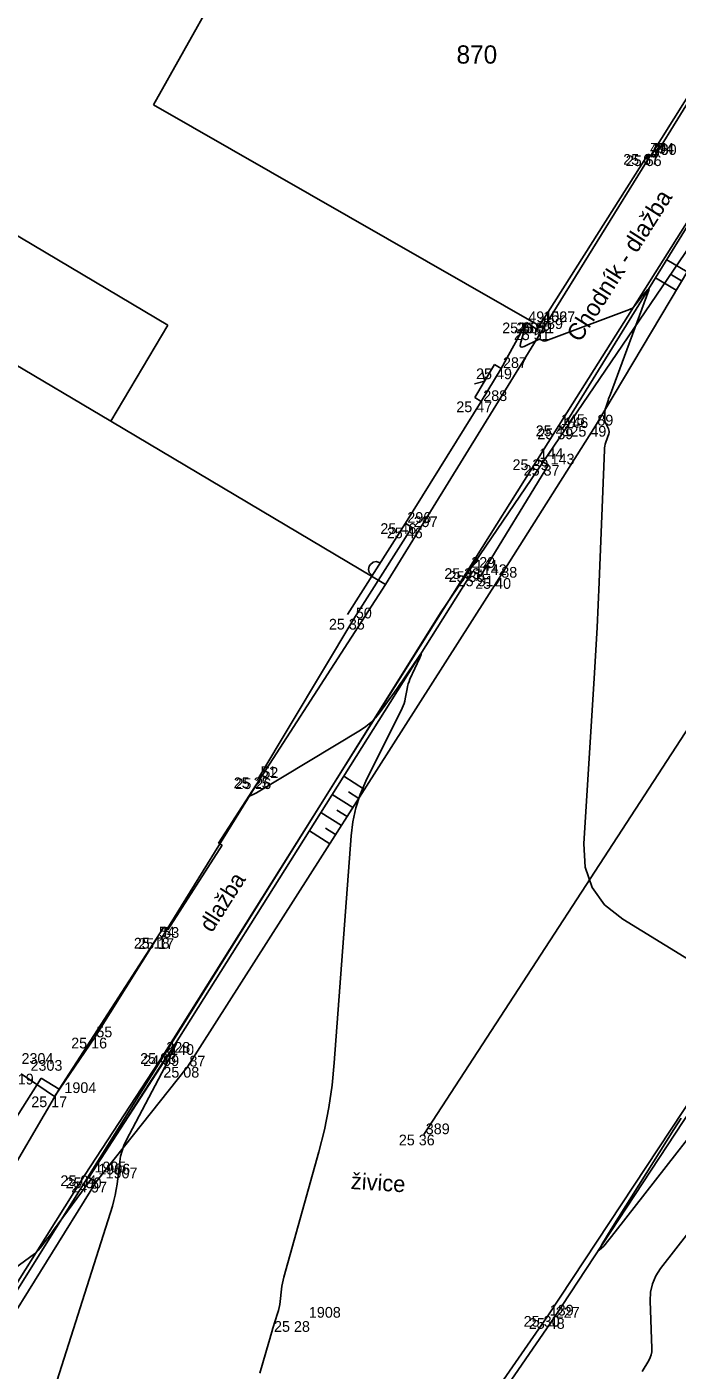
# Model space of a CAD drawing. Extents: x -702257 to -701487, y -1009871 to -1008841.
# Drawn here: x -701793.04 to -701777.89, y -1009417.21 to -1009385.88 of the extents above; entities that cross this region are included whole.
import ezdxf

# ---------------------------------------------------------------- set-up
doc = ezdxf.new("R2010")
doc.units = 0
for name, color, linetype in [('Ex_Major Contours', 7, 'Continuous'), ('Ex_Minor Contours', 7, 'Continuous'), ('Z_body', 7, 'Continuous'), ('Z_body_cisla', 7, 'Continuous'), ('Z_body_vysky_redukovane', 7, 'Continuous'), ('Z_budova', 7, 'Continuous'), ('Z_hrany_paty', 7, 'Continuous'), ('Z_katastr_cisla_stavebni', 7, 'Continuous'), ('Z_katastr_hranice', 7, 'Continuous'), ('Z_katastr_vnitrni_kresba', 7, 'Continuous'), ('Z_komunikace', 7, 'Continuous'), ('Z_obruba', 7, 'Continuous'), ('Z_ploty', 7, 'Continuous'), ('Z_ploty_znacky', 7, 'Continuous'), ('Z_popisy', 7, 'Continuous'), ('Z_technicke_srafy', 7, 'Continuous'), ('Z_VDZ12_prerusovana', 7, 'Continuous'), ('Z_vstupy', 7, 'Continuous')]:
    doc.layers.add(name, color=color, linetype=linetype)

# ---------------------------------------------------------------- blocks, each defined once
blk = doc.blocks.new('POINT_DISPLAY')
blk.add_line((0, 0), (0, 0))
blk = doc.blocks.new('Z216_1')
for p, q in [((-0.175, 0), (-0.15, 0.1)), ((-0.15, 0.1), (-0.1, 0.15)), ((-0.1, 0.15), (-0.025, 0.175)), ((-0.025, 0.175), (0.025, 0.175)), ((0.025, 0.175), (0.1, 0.15)), ((0.1, 0.15), (0.15, 0.1)), ((0.15, 0.1), (0.175, 0))]:
    blk.add_line(p, q)
blk = doc.blocks.new('Z212_1')
for p, q in [((-0.175, 0.175), (0, 0)), ((0, 0), (0.175, 0.175))]:
    blk.add_line(p, q)

msp = doc.modelspace()

# ---------------------------------------------------------------- linework, layer by layer
at = {"layer": 'Ex_Major Contours'}
msp.add_lwpolyline([(-701792.608, -1009418.304), (-701791.052, -1009413.385), (-701791.015, -1009413.259), (-701790.984, -1009413.132), (-701790.96, -1009413.003), (-701790.941, -1009412.873), (-701790.88, -1009412.35), (-701790.859, -1009412.222), (-701790.826, -1009412.096), (-701790.782, -1009411.974), (-701790.727, -1009411.856), (-701789.75, -1009409.996), (-701789.725, -1009409.948), (-701789.701, -1009409.899), (-701789.678, -1009409.851), (-701789.655, -1009409.801), (-701789.566, -1009409.604), (-701789.55, -1009409.567), (-701789.547, -1009409.553), (-701789.557, -1009409.562), (-701789.581, -1009409.595), (-701789.7, -1009409.775), (-701789.73, -1009409.82), (-701789.76, -1009409.865), (-701789.789, -1009409.91), (-701789.818, -1009409.955), (-701791.591, -1009412.706), (-701791.594, -1009412.713), (-701791.594, -1009412.719), (-701791.592, -1009412.724), (-701791.586, -1009412.729), (-701791.559, -1009412.747), (-701791.554, -1009412.752), (-701791.552, -1009412.757), (-701791.552, -1009412.763), (-701791.555, -1009412.769), (-701792.422, -1009413.951), (-701792.455, -1009413.996), (-701792.488, -1009414.04), (-701792.521, -1009414.084), (-701792.555, -1009414.128), (-701792.737, -1009414.368), (-701792.746, -1009414.38), (-701792.756, -1009414.392), (-701792.766, -1009414.404), (-701792.776, -1009414.415), (-701792.818, -1009414.461), (-701792.829, -1009414.472), (-701792.84, -1009414.483), (-701792.852, -1009414.493), (-701792.864, -1009414.502), (-701794.742, -1009415.869)], dxfattribs=at)
at = {"layer": 'Ex_Minor Contours'}
for points in [[(-701776.288, -1009408.45), (-701779.148, -1009406.697), (-701779.575, -1009406.361), (-701779.869, -1009405.956), (-701780.031, -1009405.482), (-701780.061, -1009404.939), (-701779.81, -1009400.947), (-701779.778, -1009400.418), (-701779.75, -1009399.89), (-701779.724, -1009399.361), (-701779.702, -1009398.832), (-701779.579, -1009395.748), (-701779.576, -1009395.703), (-701779.569, -1009395.659), (-701779.559, -1009395.615), (-701779.546, -1009395.572), (-701779.479, -1009395.374), (-701779.472, -1009395.345), (-701779.471, -1009395.317), (-701779.476, -1009395.288), (-701779.487, -1009395.26), (-701779.541, -1009395.15), (-701779.553, -1009395.122), (-701779.561, -1009395.093), (-701779.567, -1009395.063), (-701779.569, -1009395.033), (-701779.571, -1009394.891), (-701779.57, -1009394.858), (-701779.566, -1009394.824), (-701779.56, -1009394.792), (-701779.55, -1009394.76), (-701779.495, -1009394.598), (-701779.482, -1009394.56), (-701779.468, -1009394.523), (-701779.455, -1009394.485), (-701779.441, -1009394.448), (-701778.545, -1009392.021), (-701778.537, -1009391.994), (-701778.538, -1009391.982), (-701778.548, -1009391.987), (-701778.568, -1009392.008), (-701778.667, -1009392.124), (-701778.691, -1009392.153), (-701778.715, -1009392.183), (-701778.739, -1009392.212), (-701778.762, -1009392.242), (-701778.869, -1009392.383), (-701778.896, -1009392.414), (-701778.927, -1009392.441), (-701778.961, -1009392.462), (-701778.999, -1009392.479), (-701780.944, -1009393.205), (-701780.96, -1009393.209), (-701780.975, -1009393.21), (-701780.991, -1009393.208), (-701781.006, -1009393.203), (-701781.068, -1009393.177), (-701781.084, -1009393.172), (-701781.099, -1009393.171), (-701781.114, -1009393.173), (-701781.129, -1009393.179), (-701781.452, -1009393.337), (-701781.502, -1009393.355), (-701781.532, -1009393.349), (-701781.543, -1009393.32), (-701781.535, -1009393.269), (-701781.4, -1009392.78)], [(-701787.611, -1009417.284), (-701787.407, -1009416.562), (-701787.384, -1009416.481), (-701787.36, -1009416.4), (-701787.336, -1009416.319), (-701787.311, -1009416.238), (-701787.201, -1009415.893), (-701787.181, -1009415.824), (-701787.164, -1009415.754), (-701787.151, -1009415.683), (-701787.141, -1009415.612), (-701787.107, -1009415.324), (-701787.097, -1009415.253), (-701787.085, -1009415.182), (-701787.069, -1009415.111), (-701787.051, -1009415.041), (-701786.238, -1009412.12), (-701786.109, -1009411.607), (-701786.006, -1009411.09), (-701785.929, -1009410.569), (-701785.877, -1009410.043), (-701785.487, -1009404.755), (-701785.447, -1009404.424), (-701785.376, -1009404.101), (-701785.273, -1009403.786), (-701785.139, -1009403.48), (-701784.296, -1009401.775), (-701784.272, -1009401.722), (-701784.252, -1009401.667), (-701784.236, -1009401.611), (-701784.224, -1009401.554), (-701784.182, -1009401.323), (-701784.17, -1009401.266), (-701784.154, -1009401.209), (-701784.135, -1009401.154), (-701784.113, -1009401.1), (-701783.886, -1009400.602), (-701783.854, -1009400.525), (-701783.849, -1009400.497), (-701783.87, -1009400.517), (-701783.917, -1009400.584), (-701784.162, -1009400.951), (-701784.223, -1009401.043), (-701784.286, -1009401.133), (-701784.349, -1009401.223), (-701784.413, -1009401.313), (-701784.825, -1009401.881), (-701784.92, -1009401.999), (-701785.026, -1009402.107), (-701785.142, -1009402.203), (-701785.268, -1009402.288), (-701787.693, -1009403.747), (-701787.709, -1009403.757), (-701787.725, -1009403.765), (-701787.741, -1009403.773), (-701787.757, -1009403.781), (-701787.857, -1009403.824)], [(-701776.263, -1009410.052), (-701779.331, -1009413.989), (-701779.596, -1009414.318), (-701779.699, -1009414.416), (-701779.642, -1009414.285), (-701779.423, -1009413.925), (-701777.96, -1009411.602), (-701777.793, -1009411.338)], [(-701776.951, -1009413.147), (-701778.272, -1009414.842), (-701778.384, -1009415.014), (-701778.462, -1009415.197), (-701778.505, -1009415.391), (-701778.514, -1009415.596), (-701778.471, -1009416.71), (-701778.474, -1009416.784), (-701778.487, -1009416.854), (-701778.51, -1009416.922), (-701778.544, -1009416.987), (-701778.701, -1009417.242)]]:
    msp.add_lwpolyline(points, dxfattribs=at)
at = {"layer": 'Z_budova'}
for p, q in [((-701776.12, -1009385.08), (-701778.5, -1009388.88)), ((-701778.56, -1009388.85), (-701781.05, -1009392.78)), ((-701778.5, -1009388.88), (-701778.56, -1009388.85)), ((-701785.42, -1009399.69), (-701787.64, -1009403.39)), ((-701787.6, -1009403.41), (-701789.91, -1009407.14)), ((-701787.64, -1009403.39), (-701787.6, -1009403.41)), ((-701790.01, -1009407.13), (-701791.47, -1009409.46)), ((-701789.91, -1009407.14), (-701790.01, -1009407.13)), ((-701792.4, -1009410.83), (-701791.47, -1009409.46)), ((-701793.18, -1009410.3), (-701792.4, -1009410.83))]:
    msp.add_line(p, q, dxfattribs=at)
at = {"layer": 'Z_hrany_paty'}
for p, q in [((-701779.79, -1009395.19), (-701776.74, -1009390.06)), ((-701782.03, -1009398.74), (-701779.79, -1009395.19)), ((-701789.3, -1009410.14), (-701782.03, -1009398.74)), ((-701789.3, -1009410.14), (-701791.43, -1009412.82))]:
    msp.add_line(p, q, dxfattribs=at)
at = {"layer": 'Z_katastr_hranice'}
for p, q in [((-701783.4, -1009399.55), (-701772.27, -1009383.16)), ((-701778.42, -1009388.92), (-701777.19, -1009386.93)), ((-701781, -1009392.91), (-701778.5, -1009388.87)), ((-701778.5, -1009388.87), (-701778.42, -1009388.92)), ((-701784.68, -1009398.89), (-701781, -1009392.91)), ((-701791.09, -1009395.08), (-701793.55, -1009393.62)), ((-701784.68, -1009398.89), (-701791.09, -1009395.08)), ((-701788.58, -1009404.92), (-701784.68, -1009398.89)), ((-701809.93, -1009442), (-701783.4, -1009399.55)), ((-701789.76, -1009406.94), (-701788.49, -1009404.97)), ((-701788.49, -1009404.97), (-701788.58, -1009404.92)), ((-701792.29, -1009410.66), (-701789.85, -1009406.88)), ((-701789.85, -1009406.88), (-701789.76, -1009406.94)), ((-701795.7, -1009416.48), (-701792.29, -1009410.66))]:
    msp.add_line(p, q, dxfattribs=at)
at = {"layer": 'Z_katastr_vnitrni_kresba'}
for p, q in [((-701789.76, -1009392.84), (-701804.97, -1009383.79)), ((-701788.1, -1009384.15), (-701790.09, -1009387.7)), ((-701790.09, -1009387.7), (-701781, -1009392.91)), ((-701791.09, -1009395.08), (-701789.76, -1009392.84)), ((-701792.71, -1009410.4), (-701793.66, -1009411.9)), ((-701792.29, -1009410.66), (-701792.71, -1009410.4))]:
    msp.add_line(p, q, dxfattribs=at)
at = {"layer": 'Z_komunikace'}
for p, q in [((-701780.56, -1009395.25), (-701777.22, -1009389.85)), ((-701781.14, -1009395.97), (-701780.64, -1009395.18)), ((-701780.64, -1009395.18), (-701780.56, -1009395.25)), ((-701782.46, -1009398.68), (-701780.88, -1009396.1)), ((-701780.88, -1009396.1), (-701781.14, -1009395.97)), ((-701789.75, -1009409.87), (-701782.65, -1009398.58)), ((-701782.65, -1009398.58), (-701782.46, -1009398.68)), ((-701776.06, -1009408.61), (-701780.9, -1009415.95)), ((-701789.75, -1009409.87), (-701791.6, -1009412.72)), ((-701791.43, -1009412.82), (-701791.6, -1009412.72)), ((-701796.23, -1009420.55), (-701791.43, -1009412.82)), ((-701782.75, -1009418.62), (-701780.9, -1009415.95))]:
    msp.add_line(p, q, dxfattribs=at)
at = {"layer": 'Z_obruba'}
for p, q in [((-701780.64, -1009395.18), (-701777.2, -1009389.72)), ((-701782.73, -1009398.51), (-701781.14, -1009395.97)), ((-701789.84, -1009409.82), (-701782.73, -1009398.51)), ((-701775.96, -1009408.69), (-701780.76, -1009416)), ((-701789.84, -1009409.82), (-701791.7, -1009412.67)), ((-701791.7, -1009412.67), (-701796.54, -1009420.38)), ((-701782.63, -1009418.71), (-701780.76, -1009416))]:
    msp.add_line(p, q, dxfattribs=at)
at = {"layer": 'Z_ploty'}
for p, q in [((-701781.4, -1009392.78), (-701781.15, -1009392.94)), ((-701781.4, -1009392.78), (-701781.15, -1009392.94)), ((-701781.05, -1009392.78), (-701781.15, -1009392.94)), ((-701781.05, -1009392.78), (-701781.15, -1009392.94)), ((-701782.14, -1009393.76), (-701782.6, -1009394.53)), ((-701781.99, -1009393.85), (-701782.45, -1009394.62)), ((-701781.99, -1009393.85), (-701782.45, -1009394.62)), ((-701782.14, -1009393.76), (-701781.99, -1009393.85)), ((-701782.6, -1009394.53), (-701782.45, -1009394.62)), ((-701785.57, -1009399.59), (-701784.22, -1009397.46)), ((-701785.42, -1009399.69), (-701784.07, -1009397.56)), ((-701785.42, -1009399.69), (-701784.07, -1009397.56)), ((-701784.22, -1009397.46), (-701784.07, -1009397.56)), ((-701784.22, -1009397.46), (-701784.07, -1009397.56))]:
    msp.add_line(p, q, dxfattribs=at)
at = {"layer": 'Z_technicke_srafy'}
for p, q in [((-701777.653, -1009391.595), (-701778.126, -1009391.314)), ((-701777.908, -1009392.025), (-701778.389, -1009391.739)), ((-701777.78, -1009391.81), (-701778.019, -1009391.668)), ((-701785.174, -1009403.671), (-701785.658, -1009403.362)), ((-701785.443, -1009404.092), (-701785.924, -1009403.786)), ((-701785.309, -1009403.881), (-701785.55, -1009403.728)), ((-701785.712, -1009404.514), (-701786.19, -1009404.209)), ((-701785.578, -1009404.303), (-701785.817, -1009404.15)), ((-701785.981, -1009404.935), (-701786.456, -1009404.632)), ((-701785.846, -1009404.724), (-701786.085, -1009404.573))]:
    msp.add_line(p, q, dxfattribs=at)
at = {"layer": 'Z_VDZ12_prerusovana'}
msp.add_line((-701783.79, -1009411.72), (-701777, -1009401.27), dxfattribs=at)
msp.add_line((-701783.79, -1009411.72), (-701777, -1009401.27), dxfattribs=at)
at = {"layer": 'Z_vstupy'}
for p, q in [((-701781.4, -1009392.78), (-701781.99, -1009393.85)), ((-701781.4, -1009392.78), (-701781.99, -1009393.85)), ((-701782.45, -1009394.62), (-701784.22, -1009397.46)), ((-701782.45, -1009394.62), (-701784.22, -1009397.46))]:
    msp.add_line(p, q, dxfattribs=at)

# ---------------------------------------------------------------- block references
at = {"layer": 'Z_body'}
for p in [(-701778.56, -1009388.85), (-701778.5, -1009388.88), (-701781.4, -1009392.78), (-701781.15, -1009392.94), (-701781.05, -1009392.78), (-701781.05, -1009392.78), (-701781.99, -1009393.85), (-701782.45, -1009394.62), (-701780.64, -1009395.18), (-701780.56, -1009395.25), (-701779.79, -1009395.19), (-701781.14, -1009395.97), (-701780.88, -1009396.1), (-701784.22, -1009397.46), (-701784.07, -1009397.56), (-701782.73, -1009398.51), (-701782.65, -1009398.58), (-701782.46, -1009398.68), (-701782.03, -1009398.74), (-701785.42, -1009399.69), (-701787.64, -1009403.39), (-701787.6, -1009403.41), (-701790.01, -1009407.13), (-701789.91, -1009407.14), (-701791.47, -1009409.46), (-701789.84, -1009409.82), (-701789.75, -1009409.87), (-701789.3, -1009410.14), (-701792.4, -1009410.83), (-701783.79, -1009411.72), (-701791.7, -1009412.67), (-701791.6, -1009412.72), (-701791.43, -1009412.82), (-701786.7, -1009416.07), (-701780.9, -1009415.95), (-701780.76, -1009416)]:
    msp.add_blockref('POINT_DISPLAY', p, dxfattribs=at)
at = {"layer": 'Z_ploty_znacky'}
for name, p, rotation in [('Z212_1', (-701782.37, -1009394.145), 59.1), ('Z216_1', (-701784.901, -1009398.534), 57.6)]:
    msp.add_blockref(name, p, dxfattribs=dict(at, rotation=rotation))

# ---------------------------------------------------------------- texts
at = {"layer": 'Z_body_cisla'}
for s, p in [('47', (-701778.515, -1009388.84)), ('794', (-701778.515, -1009388.84)), ('46', (-701778.455, -1009388.87)), ('790', (-701778.455, -1009388.87)), ('49', (-701781.355, -1009392.77)), ('48', (-701781.105, -1009392.93)), ('789', (-701781.105, -1009392.93)), ('452', (-701781.005, -1009392.77)), ('1067', (-701781.005, -1009392.77)), ('287', (-701781.945, -1009393.84)), ('288', (-701782.405, -1009394.61)), ('145', (-701780.595, -1009395.17)), ('89', (-701779.745, -1009395.18)), ('146', (-701780.515, -1009395.24)), ('144', (-701781.095, -1009395.96)), ('143', (-701780.835, -1009396.09)), ('296', (-701784.175, -1009397.45)), ('297', (-701784.025, -1009397.55)), ('229', (-701782.685, -1009398.5)), ('141', (-701782.605, -1009398.57)), ('142', (-701782.415, -1009398.67)), ('88', (-701781.985, -1009398.73)), ('50', (-701785.375, -1009399.68)), ('51', (-701787.595, -1009403.38)), ('52', (-701787.555, -1009403.4)), ('54', (-701789.965, -1009407.12)), ('53', (-701789.865, -1009407.13)), ('55', (-701791.425, -1009409.45)), ('228', (-701789.795, -1009409.81)), ('140', (-701789.705, -1009409.86)), ('2304', (-701793.17, -1009410.07)), ('2303', (-701792.96, -1009410.23)), ('87', (-701789.255, -1009410.13)), ('1904', (-701792.17, -1009410.75)), ('389', (-701783.745, -1009411.71)), ('1905', (-701791.47, -1009412.6)), ('1906', (-701791.38, -1009412.65)), ('1907', (-701791.21, -1009412.74)), ('1908', (-701786.47, -1009415.99)), ('139', (-701780.855, -1009415.94)), ('227', (-701780.715, -1009415.99))]:
    msp.add_text(s, height=0.25, dxfattribs=at).set_placement(p)
at = {"layer": 'Z_body_vysky_redukovane'}
for s, p in [('25 67', (-701779.143, -1009389.1)), ('25 67', (-701779.143, -1009389.1)), ('25 66', (-701779.083, -1009389.13)), ('25 66', (-701779.083, -1009389.13)), ('25 50', (-701781.963, -1009393.03)), ('25 51', (-701781.692, -1009393.19)), ('25 51', (-701781.692, -1009393.19)), ('25 52', (-701781.633, -1009393.03)), ('25 51', (-701781.592, -1009393.03)), ('25 49', (-701782.573, -1009394.1)), ('25 47', (-701783.033, -1009394.87)), ('25 41', (-701781.182, -1009395.43)), ('25 39', (-701781.143, -1009395.5)), ('25 49', (-701780.373, -1009395.44)), ('25 39', (-701781.723, -1009396.22)), ('25 37', (-701781.463, -1009396.35)), ('25 46', (-701784.803, -1009397.71)), ('25 46', (-701784.653, -1009397.81)), ('25 33', (-701783.313, -1009398.76)), ('25 30', (-701783.213, -1009398.83)), ('25 31', (-701783.002, -1009398.93)), ('25 40', (-701782.593, -1009398.99)), ('25 35', (-701786.003, -1009399.94)), ('25 25', (-701788.223, -1009403.64)), ('25 26', (-701788.183, -1009403.66)), ('25 18', (-701790.552, -1009407.38)), ('25 17', (-701790.452, -1009407.39)), ('25 16', (-701792.012, -1009409.71)), ('25 08', (-701790.403, -1009410.07)), ('24 99', (-701790.333, -1009410.12)), ('25 19', (-701793.722, -1009410.55)), ('25 08', (-701789.863, -1009410.39)), ('25 17', (-701792.942, -1009411.08)), ('25 36', (-701784.373, -1009411.97)), ('25 04', (-701792.263, -1009412.92)), ('25 00', (-701792.142, -1009412.97)), ('24 97', (-701792.013, -1009413.07)), ('25 28', (-701787.283, -1009416.32)), ('25 30', (-701781.463, -1009416.2)), ('25 48', (-701781.343, -1009416.25))]:
    msp.add_text(s, height=0.25, dxfattribs=at).set_placement(p)
at = {"layer": 'Z_katastr_cisla_stavebni'}
msp.add_text('870', height=0.425, dxfattribs=at).set_placement((-701783.028, -1009386.74))
at = {"layer": 'Z_popisy'}
for s, height, rotation, p in [('Chodník - dlažba', 0.4, 57.6, (-701780.149, -1009393.261)), ('dlažba', 0.38, 57.6, (-701788.73, -1009407.026)), ('živice', 0.38, 356.4, (-701785.5, -1009412.987))]:
    msp.add_text(s, height=height, rotation=rotation, dxfattribs=at).set_placement(p)

doc.saveas('drawing.dxf')
